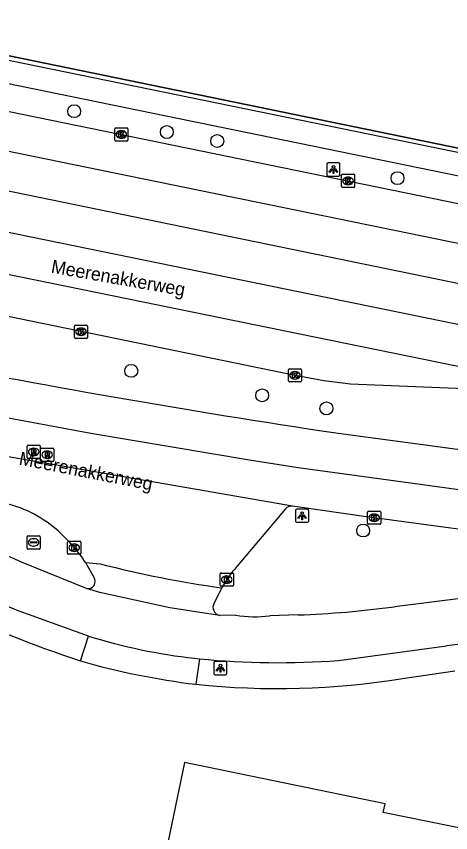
# Model space of a CAD drawing. Extents: x 157692 to 159670, y 381454 to 383289.
# Drawn here: x 157967 to 157999.9, y 382186.1 to 382247.9 of the extents above; entities that cross this region are included whole.
import ezdxf

# ---------------------------------------------------------------- set-up
doc = ezdxf.new("R2010")
doc.units = 0
for name, color, linetype in [('IMGEO_Boom', 7, 'Continuous'), ('IMGEO_Fietspad_gesloten', 7, 'Continuous'), ('IMGEO_Gasput', 7, 'Continuous'), ('IMGEO_Grasland_overig', 7, 'Continuous'), ('IMGEO_Hek', 7, 'Continuous'), ('IMGEO_Kolk', 7, 'Continuous'), ('IMGEO_Lichtpunt', 7, 'Continuous'), ('IMGEO_Openbare_ruimte_label', 7, 'Continuous'), ('IMGEO_Pand', 7, 'Continuous'), ('IMGEO_Rijbaan_lokaal_open', 7, 'Continuous'), ('IMGEO_Rijbaan_regionaal_gesloten', 7, 'Continuous'), ('IMGEO_Rioolput', 7, 'Continuous'), ('IMGEO_Voetpad_open', 7, 'Continuous')]:
    doc.layers.add(name, color=color, linetype=linetype)

msp = doc.modelspace()

# ---------------------------------------------------------------- linework, layer by layer
at = {"layer": 'IMGEO_Boom'}
for centre in [(157971.394, 382240.702), (157978.404, 382239.12), (157982.216, 382238.444), (157995.856, 382235.631), (157975.709, 382221.036), (157985.619, 382219.18), (157990.48, 382218.192), (157993.261, 382208.945)]:
    msp.add_circle(centre, 0.489, dxfattribs=at)
at = {"layer": 'IMGEO_Fietspad_gesloten'}
for points in [[(157972.315, 382204.553), (157967.403, 382206.545), (157963.805, 382208.157)], [(157972.482, 382200.955), (157967.02, 382202.918), (157961.093, 382205.434)], [(158000.456, 382203.768), (157995.639, 382203.176)], [(157983.607, 382202.523), (157982.417, 382202.519)], [(157988.334, 382202.548), (157986.206, 382202.491)], [(157991.404, 382199.107), (157999.57, 382200.21)]]:
    msp.add_lwpolyline(points, dxfattribs=at)
for centre, radius, start, end in [((157985.473, 382278.623), 76.128, 272.1534, 277.67371), ((157985.02, 382211.74), 9.324, 261.28276, 277.30641), ((158005.888, 382152.031), 48.591, 81.16578, 97.47049), ((157986.831, 382260.18), 61.244, 264.41262, 274.2823)]:
    msp.add_arc(centre, radius, start, end, dxfattribs=at)
at = {"layer": 'IMGEO_Gasput'}
for p, q in [((157967.825, 382207.62), (157967.825, 382208.472)), ((157967.9, 382208.546), (157968.752, 382208.546)), ((157968.084, 382208.04), (157968.084, 382208.052)), ((157968.127, 382208.089), (157968.525, 382208.089)), ((157968.313, 382208.326), (157968.338, 382208.326)), ((157968.568, 382208.052), (157968.568, 382208.04)), ((157968.826, 382208.472), (157968.826, 382207.62)), ((157968.752, 382207.546), (157967.9, 382207.546)), ((157968.522, 382208.003), (157968.124, 382208.003)), ((157968.336, 382207.766), (157968.311, 382207.766))]:
    msp.add_line(p, q, dxfattribs=at)
for points in [[(157967.825, 382207.62), (157967.825, 382208.472)], [(157967.9, 382208.546), (157968.752, 382208.546)], [(157968.826, 382208.472), (157968.826, 382207.62)], [(157968.752, 382207.546), (157967.9, 382207.546)]]:
    msp.add_lwpolyline(points, dxfattribs=at)
for centre, radius, start, end in [((157967.902, 382208.47), 0.0765, 91.55205, 178.44795), ((157967.902, 382208.47), 0.0765, 91.55205, 178.44795), ((157968.124, 382208.049), 0.0403, 85.87752, 175.75265), ((157968.121, 382208.039), 0.0366, 178.93798, 274.71019), ((157968.525, 382208.046), 0.043, 264.86636, 352.45326), ((157968.529, 382208.051), 0.0386, 1.73085, 96.63898), ((157968.75, 382208.47), 0.0765, 1.55205, 88.44795), ((157968.75, 382208.47), 0.0765, 1.55205, 88.44795), ((157967.902, 382207.622), 0.0765, 181.55205, 268.44795), ((157967.902, 382207.622), 0.0765, 181.55205, 268.44795), ((157968.75, 382207.622), 0.0765, 271.55205, 358.44795), ((157968.75, 382207.622), 0.0765, 271.55205, 358.44795)]:
    msp.add_arc(centre, radius, start, end, dxfattribs=at)
for centre, major_axis, ratio, start_param, end_param in [((157968.312, 382208.046), (-0.387, 0.002), 0.722429, 4.712389, 7.853982), ((157968.337, 382208.046), (-0.39, 0.002), 0.717154, 1.570796, 4.712389)]:
    msp.add_ellipse(centre, major_axis=major_axis, ratio=ratio, start_param=start_param, end_param=end_param, dxfattribs=at)
at = {"layer": 'IMGEO_Grasland_overig'}
msp.add_lwpolyline([(157893.686, 382278.441), (157908.345, 382268.167), (157916.848, 382263.754), (157928.758, 382257.878), (157939.464, 382250.486), (158076.245, 382222.292), (158077.524, 382222.097), (158103.667, 382210.061)], dxfattribs=at)
at = {"layer": 'IMGEO_Hek'}
msp.add_lwpolyline([(158076.245, 382222.292), (157939.464, 382250.486), (157928.758, 382257.878), (157916.848, 382263.754)], dxfattribs=at)
at = {"layer": 'IMGEO_Kolk'}
for p, q in [((157974.46, 382238.514), (157974.46, 382239.366)), ((157974.535, 382239.44), (157975.387, 382239.44)), ((157974.948, 382239.22), (157974.973, 382239.22)), ((157975.461, 382239.366), (157975.461, 382238.514)), ((157975.387, 382238.44), (157974.535, 382238.44)), ((157974.971, 382238.66), (157974.946, 382238.66)), ((157991.614, 382234.999), (157991.614, 382235.851)), ((157991.689, 382235.925), (157992.541, 382235.925)), ((157992.615, 382235.851), (157992.615, 382234.999)), ((157992.102, 382235.705), (157992.127, 382235.705)), ((157992.541, 382234.925), (157991.689, 382234.925)), ((157992.125, 382235.145), (157992.1, 382235.145)), ((157971.41, 382223.573), (157971.41, 382224.425)), ((157971.485, 382224.499), (157972.337, 382224.499)), ((157971.898, 382224.279), (157971.923, 382224.279)), ((157972.411, 382224.425), (157972.411, 382223.573)), ((157972.337, 382223.499), (157971.485, 382223.499)), ((157971.921, 382223.719), (157971.896, 382223.719)), ((157987.601, 382220.271), (157987.601, 382221.123)), ((157987.676, 382221.197), (157988.528, 382221.197)), ((157988.602, 382221.123), (157988.602, 382220.271)), ((157988.112, 382220.417), (157988.087, 382220.417)), ((157988.089, 382220.977), (157988.114, 382220.977)), ((157988.528, 382220.197), (157987.676, 382220.197)), ((157993.593, 382209.49), (157993.593, 382210.342)), ((157993.668, 382210.416), (157994.52, 382210.416)), ((157994.081, 382210.196), (157994.106, 382210.196)), ((157994.594, 382210.342), (157994.594, 382209.49)), ((157994.52, 382209.416), (157993.668, 382209.416)), ((157994.104, 382209.636), (157994.079, 382209.636)), ((157970.899, 382207.219), (157970.899, 382208.071)), ((157970.974, 382208.145), (157971.826, 382208.145)), ((157971.9, 382208.071), (157971.9, 382207.219)), ((157971.387, 382207.925), (157971.412, 382207.925)), ((157971.826, 382207.145), (157970.974, 382207.145)), ((157971.41, 382207.365), (157971.385, 382207.365)), ((157982.439, 382204.802), (157982.439, 382205.654)), ((157982.514, 382205.728), (157983.366, 382205.728)), ((157983.44, 382205.654), (157983.44, 382204.802)), ((157982.95, 382204.948), (157982.925, 382204.948)), ((157982.927, 382205.508), (157982.952, 382205.508)), ((157983.366, 382204.728), (157982.514, 382204.728))]:
    msp.add_line(p, q, dxfattribs=at)
for points in [[(157974.46, 382238.514), (157974.46, 382239.366)], [(157974.535, 382239.44), (157975.387, 382239.44)], [(157974.781, 382239.14), (157974.904, 382239.14), (157974.904, 382238.989), (157975.034, 382239.14), (157975.198, 382239.14), (157975.052, 382238.989), (157975.205, 382238.74), (157975.053, 382238.74), (157974.968, 382238.904), (157974.904, 382238.837), (157974.904, 382238.74), (157974.781, 382238.74), (157974.781, 382239.14)], [(157975.461, 382239.366), (157975.461, 382238.514)], [(157975.387, 382238.44), (157974.535, 382238.44)], [(157991.614, 382234.999), (157991.614, 382235.851)], [(157991.689, 382235.925), (157992.541, 382235.925)], [(157992.615, 382235.851), (157992.615, 382234.999)], [(157991.935, 382235.625), (157992.058, 382235.625), (157992.058, 382235.474), (157992.188, 382235.625), (157992.352, 382235.625), (157992.206, 382235.474), (157992.359, 382235.225), (157992.207, 382235.225), (157992.122, 382235.389), (157992.058, 382235.322), (157992.058, 382235.225), (157991.935, 382235.225), (157991.935, 382235.625)], [(157992.541, 382234.925), (157991.689, 382234.925)], [(157971.41, 382223.573), (157971.41, 382224.425)], [(157971.485, 382224.499), (157972.337, 382224.499)], [(157971.731, 382224.199), (157971.854, 382224.199), (157971.854, 382224.048), (157971.984, 382224.199), (157972.148, 382224.199), (157972.002, 382224.048), (157972.155, 382223.799), (157972.003, 382223.799), (157971.918, 382223.963), (157971.854, 382223.896), (157971.854, 382223.799), (157971.731, 382223.799), (157971.731, 382224.199)], [(157972.411, 382224.425), (157972.411, 382223.573)], [(157972.337, 382223.499), (157971.485, 382223.499)], [(157987.601, 382220.271), (157987.601, 382221.123)], [(157987.676, 382221.197), (157988.528, 382221.197)], [(157988.602, 382221.123), (157988.602, 382220.271)], [(157987.922, 382220.897), (157988.045, 382220.897), (157988.045, 382220.746), (157988.175, 382220.897), (157988.339, 382220.897), (157988.193, 382220.746), (157988.346, 382220.497), (157988.194, 382220.497), (157988.109, 382220.661), (157988.045, 382220.594), (157988.045, 382220.497), (157987.922, 382220.497), (157987.922, 382220.897)], [(157988.528, 382220.197), (157987.676, 382220.197)], [(157993.593, 382209.49), (157993.593, 382210.342)], [(157993.668, 382210.416), (157994.52, 382210.416)], [(157993.914, 382210.116), (157994.037, 382210.116), (157994.037, 382209.965), (157994.167, 382210.116), (157994.331, 382210.116), (157994.185, 382209.965), (157994.338, 382209.716), (157994.186, 382209.716), (157994.101, 382209.88), (157994.037, 382209.813), (157994.037, 382209.716), (157993.914, 382209.716), (157993.914, 382210.116)], [(157994.594, 382210.342), (157994.594, 382209.49)], [(157994.52, 382209.416), (157993.668, 382209.416)], [(157970.899, 382207.219), (157970.899, 382208.071)], [(157970.974, 382208.145), (157971.826, 382208.145)], [(157971.9, 382208.071), (157971.9, 382207.219)], [(157971.22, 382207.845), (157971.343, 382207.845), (157971.343, 382207.694), (157971.473, 382207.845), (157971.637, 382207.845), (157971.491, 382207.694), (157971.644, 382207.445), (157971.492, 382207.445), (157971.407, 382207.609), (157971.343, 382207.542), (157971.343, 382207.445), (157971.22, 382207.445), (157971.22, 382207.845)], [(157971.826, 382207.145), (157970.974, 382207.145)], [(157982.439, 382204.802), (157982.439, 382205.654)], [(157982.514, 382205.728), (157983.366, 382205.728)], [(157983.44, 382205.654), (157983.44, 382204.802)], [(157982.76, 382205.428), (157982.883, 382205.428), (157982.883, 382205.277), (157983.013, 382205.428), (157983.177, 382205.428), (157983.031, 382205.277), (157983.184, 382205.028), (157983.032, 382205.028), (157982.947, 382205.192), (157982.883, 382205.125), (157982.883, 382205.028), (157982.76, 382205.028), (157982.76, 382205.428)], [(157983.366, 382204.728), (157982.514, 382204.728)]]:
    msp.add_lwpolyline(points, dxfattribs=at)
for centre, start, end in [((157974.537, 382239.364), 91.55205, 178.44795), ((157974.537, 382239.364), 91.55205, 178.44795), ((157975.385, 382239.364), 1.55205, 88.44795), ((157975.385, 382239.364), 1.55205, 88.44795), ((157974.537, 382238.516), 181.55205, 268.44795), ((157974.537, 382238.516), 181.55205, 268.44795), ((157975.385, 382238.516), 271.55205, 358.44795), ((157975.385, 382238.516), 271.55205, 358.44795), ((157991.691, 382235.849), 91.55205, 178.44795), ((157991.691, 382235.849), 91.55205, 178.44795), ((157992.539, 382235.849), 1.55205, 88.44795), ((157992.539, 382235.849), 1.55205, 88.44795), ((157991.691, 382235.001), 181.55205, 268.44795), ((157991.691, 382235.001), 181.55205, 268.44795), ((157992.539, 382235.001), 271.55205, 358.44795), ((157992.539, 382235.001), 271.55205, 358.44795), ((157971.487, 382224.423), 91.55205, 178.44795), ((157971.487, 382224.423), 91.55205, 178.44795), ((157972.335, 382224.423), 1.55205, 88.44795), ((157972.335, 382224.423), 1.55205, 88.44795), ((157971.487, 382223.575), 181.55205, 268.44795), ((157971.487, 382223.575), 181.55205, 268.44795), ((157972.335, 382223.575), 271.55205, 358.44795), ((157972.335, 382223.575), 271.55205, 358.44795), ((157987.678, 382221.121), 91.55205, 178.44795), ((157987.678, 382221.121), 91.55205, 178.44795), ((157988.526, 382221.121), 1.55205, 88.44795), ((157988.526, 382221.121), 1.55205, 88.44795), ((157987.678, 382220.273), 181.55205, 268.44795), ((157987.678, 382220.273), 181.55205, 268.44795), ((157988.526, 382220.273), 271.55205, 358.44795), ((157988.526, 382220.273), 271.55205, 358.44795), ((157993.67, 382210.34), 91.55205, 178.44795), ((157993.67, 382210.34), 91.55205, 178.44795), ((157994.518, 382210.34), 1.55205, 88.44795), ((157994.518, 382210.34), 1.55205, 88.44795), ((157993.67, 382209.492), 181.55205, 268.44795), ((157993.67, 382209.492), 181.55205, 268.44795), ((157994.518, 382209.492), 271.55205, 358.44795), ((157994.518, 382209.492), 271.55205, 358.44795), ((157970.976, 382208.069), 91.55205, 178.44795), ((157970.976, 382208.069), 91.55205, 178.44795), ((157971.824, 382208.069), 1.55205, 88.44795), ((157971.824, 382208.069), 1.55205, 88.44795), ((157970.976, 382207.221), 181.55205, 268.44795), ((157970.976, 382207.221), 181.55205, 268.44795), ((157971.824, 382207.221), 271.55205, 358.44795), ((157971.824, 382207.221), 271.55205, 358.44795), ((157982.516, 382205.652), 91.55205, 178.44795), ((157982.516, 382205.652), 91.55205, 178.44795), ((157983.364, 382205.652), 1.55205, 88.44795), ((157983.364, 382205.652), 1.55205, 88.44795), ((157982.516, 382204.804), 181.55205, 268.44795), ((157982.516, 382204.804), 181.55205, 268.44795), ((157983.364, 382204.804), 271.55205, 358.44795), ((157983.364, 382204.804), 271.55205, 358.44795)]:
    msp.add_arc(centre, 0.0765, start, end, dxfattribs=at)
for centre, major_axis, ratio, start_param, end_param in [((157974.947, 382238.94), (-0.387, 0.002), 0.722429, 4.712389, 7.853982), ((157974.972, 382238.94), (-0.39, 0.002), 0.717154, 1.570796, 4.712389), ((157992.101, 382235.425), (-0.387, 0.002), 0.722429, 4.712389, 7.853982), ((157992.126, 382235.425), (-0.39, 0.002), 0.717154, 1.570796, 4.712389), ((157971.897, 382223.999), (-0.387, 0.002), 0.722429, 4.712389, 7.853982), ((157971.922, 382223.999), (-0.39, 0.002), 0.717154, 1.570796, 4.712389), ((157988.088, 382220.697), (-0.387, 0.002), 0.722429, 4.712389, 7.853982), ((157988.113, 382220.697), (-0.39, 0.002), 0.717154, 1.570796, 4.712389), ((157994.08, 382209.916), (-0.387, 0.002), 0.722429, 4.712389, 7.853982), ((157994.105, 382209.916), (-0.39, 0.002), 0.717154, 1.570796, 4.712389), ((157971.386, 382207.645), (-0.387, 0.002), 0.722429, 4.712389, 7.853982), ((157971.411, 382207.645), (-0.39, 0.002), 0.717154, 1.570796, 4.712389), ((157982.926, 382205.228), (-0.387, 0.002), 0.722429, 4.712389, 7.853982), ((157982.951, 382205.228), (-0.39, 0.002), 0.717154, 1.570796, 4.712389)]:
    msp.add_ellipse(centre, major_axis=major_axis, ratio=ratio, start_param=start_param, end_param=end_param, dxfattribs=at)
at = {"layer": 'IMGEO_Lichtpunt'}
for p, q in [((157990.509, 382236.69), (157990.509, 382235.883)), ((157990.509, 382236.69), (157990.509, 382235.883)), ((157991.411, 382236.785), (157990.603, 382236.785)), ((157991.411, 382236.785), (157990.603, 382236.785)), ((157991.505, 382235.883), (157991.505, 382236.69)), ((157991.505, 382235.883), (157991.505, 382236.69)), ((157990.603, 382235.789), (157991.411, 382235.789)), ((157990.603, 382235.789), (157991.411, 382235.789)), ((157989.042, 382210.567), (157988.234, 382210.567)), ((157989.042, 382210.567), (157988.234, 382210.567)), ((157988.14, 382210.472), (157988.14, 382209.665)), ((157988.14, 382210.472), (157988.14, 382209.665)), ((157989.136, 382209.665), (157989.136, 382210.472)), ((157989.136, 382209.665), (157989.136, 382210.472)), ((157988.234, 382209.571), (157989.042, 382209.571)), ((157988.234, 382209.571), (157989.042, 382209.571)), ((157981.959, 382198.929), (157981.959, 382198.122)), ((157981.959, 382198.929), (157981.959, 382198.122)), ((157982.861, 382199.024), (157982.053, 382199.024)), ((157982.861, 382199.024), (157982.053, 382199.024)), ((157982.955, 382198.122), (157982.955, 382198.929)), ((157982.955, 382198.122), (157982.955, 382198.929)), ((157982.053, 382198.028), (157982.861, 382198.028)), ((157982.053, 382198.028), (157982.861, 382198.028))]:
    msp.add_line(p, q, dxfattribs=at)
for points in [[(157990.883, 382236.354), (157990.922, 382236.326), (157990.734, 382236.064), (157990.696, 382236.091), (157990.883, 382236.354)], [(157990.985, 382236.306), (157991.032, 382236.306), (157991.032, 382235.984), (157990.985, 382235.984), (157990.985, 382236.306)], [(157991.095, 382236.326), (157991.133, 382236.353), (157991.32, 382236.091), (157991.281, 382236.063), (157991.095, 382236.326)], [(157988.514, 382210.136), (157988.553, 382210.108), (157988.365, 382209.846), (157988.327, 382209.873), (157988.514, 382210.136)], [(157988.616, 382210.088), (157988.663, 382210.088), (157988.663, 382209.766), (157988.616, 382209.766), (157988.616, 382210.088)], [(157988.726, 382210.108), (157988.764, 382210.135), (157988.951, 382209.873), (157988.912, 382209.845), (157988.726, 382210.108)], [(157982.333, 382198.593), (157982.372, 382198.565), (157982.184, 382198.303), (157982.146, 382198.33), (157982.333, 382198.593)], [(157982.435, 382198.545), (157982.482, 382198.545), (157982.482, 382198.223), (157982.435, 382198.223), (157982.435, 382198.545)], [(157982.545, 382198.565), (157982.583, 382198.592), (157982.77, 382198.33), (157982.731, 382198.302), (157982.545, 382198.565)]]:
    msp.add_lwpolyline(points, dxfattribs=at)
for centre in [(157991.008, 382236.488), (157988.639, 382210.27), (157982.458, 382198.727)]:
    msp.add_circle(centre, 0.0994, dxfattribs=at)
for centre, start, end in [((157990.603, 382236.69), 90, 180), ((157990.603, 382236.69), 90, 180), ((157991.411, 382236.69), 0, 90), ((157991.411, 382236.69), 0, 90), ((157990.603, 382235.883), 180, 270), ((157990.603, 382235.883), 180, 270), ((157991.411, 382235.883), 270, 0), ((157991.411, 382235.883), 270, 360), ((157988.234, 382210.472), 90, 180), ((157988.234, 382210.472), 90, 180), ((157989.042, 382210.472), 0, 90), ((157989.042, 382210.472), 0, 90), ((157988.234, 382209.665), 180, 270), ((157988.234, 382209.665), 180, 270), ((157989.042, 382209.665), 270, 0), ((157989.042, 382209.665), 270, 360), ((157982.053, 382198.929), 90, 180), ((157982.053, 382198.929), 90, 180), ((157982.861, 382198.929), 0, 90), ((157982.861, 382198.929), 0, 90), ((157982.053, 382198.122), 180, 270), ((157982.053, 382198.122), 180, 270), ((157982.861, 382198.122), 270, 0), ((157982.861, 382198.122), 270, 360)]:
    msp.add_arc(centre, 0.0946, start, end, dxfattribs=at)
at = {"layer": 'IMGEO_Pand'}
msp.add_lwpolyline([(158125.007, 382160.95), (158000, 382186.53), (157994.77, 382187.6), (157994.924, 382188.242), (157979.752, 382191.371), (157976.517, 382175.795)], dxfattribs=at)
at = {"layer": 'IMGEO_Rijbaan_lokaal_open'}
for points in [[(157972.257, 382206.532), (157972.878, 382205.423)], [(157982.417, 382202.519), (157978.621, 382203.09), (157973.339, 382204.241), (157972.315, 382204.553)], [(157982.577, 382204.611), (157981.987, 382203.467)], [(157971.868, 382199.069), (157972.482, 382200.955)], [(157980.499, 382199.267), (157980.868, 382199.227)], [(157980.868, 382199.227), (157980.595, 382197.301)]]:
    msp.add_lwpolyline(points, dxfattribs=at)
for centre, radius, start, end in [((157972.432, 382205.094), 0.554, 257.77442, 36.40963), ((157982.524, 382203.139), 0.629, 148.58211, 260.21469), ((157985.378, 382242.323), 43.332, 252.68531, 263.53449), ((157987.559, 382254.097), 57.221, 254.08498, 263.00995)]:
    msp.add_arc(centre, radius, start, end, dxfattribs=at)
at = {"layer": 'IMGEO_Rijbaan_regionaal_gesloten'}
for points in [[(157946.89, 382244.694), (158071.725, 382219.098)], [(158086.264, 382213.087), (157933.406, 382244.416)], [(157932.141, 382241.702), (158099.184, 382207.368)], [(158343.515, 382152.527), (158327.525, 382155.488), (158318.888, 382157.281), (158300.095, 382161.181), (158268.722, 382167.572), (158256.931, 382169.996), (158249.098, 382171.701), (158237.46, 382174.557), (158225.893, 382177.689), (158214.463, 382180.529), (158188.034, 382186.098), (157930.794, 382238.814)], [(157929.435, 382235.902), (158010.817, 382219.277)], [(158008.786, 382219.466), (158005.318, 382219.673), (158000.291, 382219.697), (157992.3, 382220.036), (157990.292, 382220.285), (157988.102, 382220.697), (157928.091, 382233.019)], [(157925.243, 382226.645), (157933.19, 382224.57), (157944.252, 382221.934), (157952.268, 382220.278), (157960.705, 382218.534), (157972.663, 382216.316), (157984.656, 382214.298), (157988.349, 382213.708), (157992.778, 382213.101), (157996.273, 382212.623), (158008.566, 382210.941), (158012.613, 382210.388), (158016.646, 382209.742), (158020.135, 382209.234), (158024.234, 382208.503), (158031.467, 382207.214), (158206.473, 382171.3), (158336.056, 382144.815)], [(157987.907, 382210.788), (157958.25, 382215.936), (157943.073, 382218.891), (157935.016, 382220.849)], [(157991.181, 382216.341), (158004.32, 382214.58)], [(157987.384, 382210.584), (157983.699, 382206.213)], [(158017.408, 382206.666), (158006.068, 382208.301), (157994.094, 382209.916), (157993.669, 382209.969), (157987.907, 382210.788)], [(157972.257, 382206.532), (157973.373, 382206.418)]]:
    msp.add_lwpolyline(points, dxfattribs=at)
for centre, radius, start, end in [((158092.755, 382896.846), 688.044, 258.695808, 261.510563), ((157963.795, 382201.609), 9.707, 50.07818, 77.14146), ((157987.841, 382210.185), 0.606, 83.7288, 138.88847), ((157961.452, 382199.211), 13.052, 34.12044, 48.94602), ((157993.296, 382283.552), 79.666, 255.51763, 262.26742), ((157989.305, 382201.093), 7.592, 137.59293, 152.39423)]:
    msp.add_arc(centre, radius, start, end, dxfattribs=at)
at = {"layer": 'IMGEO_Rioolput'}
for p, q in [((157967.832, 382214.473), (157967.832, 382215.325)), ((157967.907, 382215.399), (157968.759, 382215.399)), ((157968.32, 382215.179), (157968.345, 382215.179)), ((157968.833, 382215.325), (157968.833, 382214.473)), ((157968.852, 382214.256), (157968.852, 382215.108)), ((157968.927, 382215.182), (157969.779, 382215.182)), ((157969.34, 382214.962), (157969.365, 382214.962)), ((157969.853, 382215.108), (157969.853, 382214.256)), ((157968.759, 382214.399), (157967.907, 382214.399)), ((157968.343, 382214.619), (157968.318, 382214.619)), ((157969.363, 382214.402), (157969.338, 382214.402)), ((157969.779, 382214.182), (157968.927, 382214.182))]:
    msp.add_line(p, q, dxfattribs=at)
for points in [[(157967.832, 382214.473), (157967.832, 382215.325)], [(157967.907, 382215.399), (157968.759, 382215.399)], [(157968.421, 382215.097), (157968.169, 382215.099), (157968.169, 382214.699)], [(157968.169, 382214.699), (157968.293, 382214.699), (157968.293, 382214.861), (157968.304, 382214.861)], [(157968.347, 382215.018), (157968.293, 382215.018), (157968.293, 382214.937)], [(157968.293, 382214.937), (157968.345, 382214.937)], [(157968.351, 382214.832), (157968.422, 382214.699), (157968.562, 382214.699), (157968.497, 382214.825)], [(157968.833, 382215.325), (157968.833, 382214.473)], [(157968.852, 382214.256), (157968.852, 382215.108)], [(157968.927, 382215.182), (157969.779, 382215.182)], [(157969.441, 382214.88), (157969.189, 382214.882), (157969.189, 382214.482)], [(157969.853, 382215.108), (157969.853, 382214.256)], [(157968.759, 382214.399), (157967.907, 382214.399)], [(157969.189, 382214.482), (157969.313, 382214.482), (157969.313, 382214.644), (157969.324, 382214.644)], [(157969.367, 382214.801), (157969.313, 382214.801), (157969.313, 382214.72)], [(157969.313, 382214.72), (157969.365, 382214.72)], [(157969.371, 382214.615), (157969.442, 382214.482), (157969.582, 382214.482), (157969.517, 382214.608)], [(157969.779, 382214.182), (157968.927, 382214.182)]]:
    msp.add_lwpolyline(points, dxfattribs=at)
for centre, radius, start, end in [((157967.909, 382215.323), 0.0765, 91.55205, 178.44795), ((157967.909, 382215.323), 0.0765, 91.55205, 178.44795), ((157968.303, 382214.808), 0.0533, 26.02933, 88.69889), ((157968.329, 382215.126), 0.19, 274.7715, 282.96867), ((157968.353, 382214.922), 0.0964, 77.00612, 93.18647), ((157968.367, 382214.979), 0.0378, 276.66336, 79.67722), ((157968.42, 382214.987), 0.109, 350.36119, 89.41601), ((157968.418, 382214.987), 0.112, 277.58423, 350.98172), ((157968.402, 382214.772), 0.108, 29.51342, 73.79051), ((157968.757, 382215.323), 0.0765, 1.55205, 88.44795), ((157968.757, 382215.323), 0.0765, 1.55205, 88.44795), ((157968.929, 382215.106), 0.0765, 91.55205, 178.44795), ((157968.929, 382215.106), 0.0765, 91.55205, 178.44795), ((157969.44, 382214.77), 0.109, 350.36119, 89.41601), ((157969.777, 382215.106), 0.0765, 1.55205, 88.44795), ((157969.777, 382215.106), 0.0765, 1.55205, 88.44795), ((157967.909, 382214.475), 0.0765, 181.55205, 268.44795), ((157967.909, 382214.475), 0.0765, 181.55205, 268.44795), ((157968.757, 382214.475), 0.0765, 271.55205, 358.44795), ((157968.757, 382214.475), 0.0765, 271.55205, 358.44795), ((157968.929, 382214.258), 0.0765, 181.55205, 268.44795), ((157968.929, 382214.258), 0.0765, 181.55205, 268.44795), ((157969.323, 382214.591), 0.0533, 26.02933, 88.69889), ((157969.349, 382214.909), 0.19, 274.7715, 282.96867), ((157969.373, 382214.705), 0.0964, 77.00612, 93.18647), ((157969.387, 382214.762), 0.0378, 276.66336, 79.67722), ((157969.438, 382214.77), 0.112, 277.58423, 350.98172), ((157969.422, 382214.555), 0.108, 29.51342, 73.79051), ((157969.777, 382214.258), 0.0765, 271.55205, 358.44795), ((157969.777, 382214.258), 0.0765, 271.55205, 358.44795)]:
    msp.add_arc(centre, radius, start, end, dxfattribs=at)
for centre, major_axis, ratio, start_param, end_param in [((157968.319, 382214.899), (-0.387, 0.002), 0.722429, 4.712389, 7.853982), ((157968.344, 382214.899), (-0.39, 0.002), 0.717154, 1.570796, 4.712389), ((157969.339, 382214.682), (-0.387, 0.002), 0.722429, 4.712389, 7.853982), ((157969.364, 382214.682), (-0.39, 0.002), 0.717154, 1.570796, 4.712389)]:
    msp.add_ellipse(centre, major_axis=major_axis, ratio=ratio, start_param=start_param, end_param=end_param, dxfattribs=at)
at = {"layer": 'IMGEO_Voetpad_open'}
for points in [[(157933.182, 382254.34), (157939.571, 382250.089), (158076.975, 382221.903), (158102.013, 382210.4), (158103.667, 382210.061)], [(158193.233, 382189.844), (158101.447, 382208.648), (158076.404, 382220.194), (157938.825, 382248.42), (157937.518, 382249.285)], [(157996.236, 382197.74), (158000.185, 382198.327)]]:
    msp.add_lwpolyline(points, dxfattribs=at)
for centre, radius, start, end in [((158009.307, 382309.87), 116.955, 245.69835, 251.33027), ((157986.777, 382255.899), 58.923, 263.97767, 279.23775)]:
    msp.add_arc(centre, radius, start, end, dxfattribs=at)

# ---------------------------------------------------------------- texts
at = {"layer": 'IMGEO_Openbare_ruimte_label'}
for rotation, p in [(349.92567, (157969.597, 382228.482)), (348.92613, (157967.164, 382213.944))]:
    msp.add_text('Meerenakkerweg', height=1, rotation=rotation, dxfattribs=at).set_placement(p)

doc.saveas('drawing.dxf')
